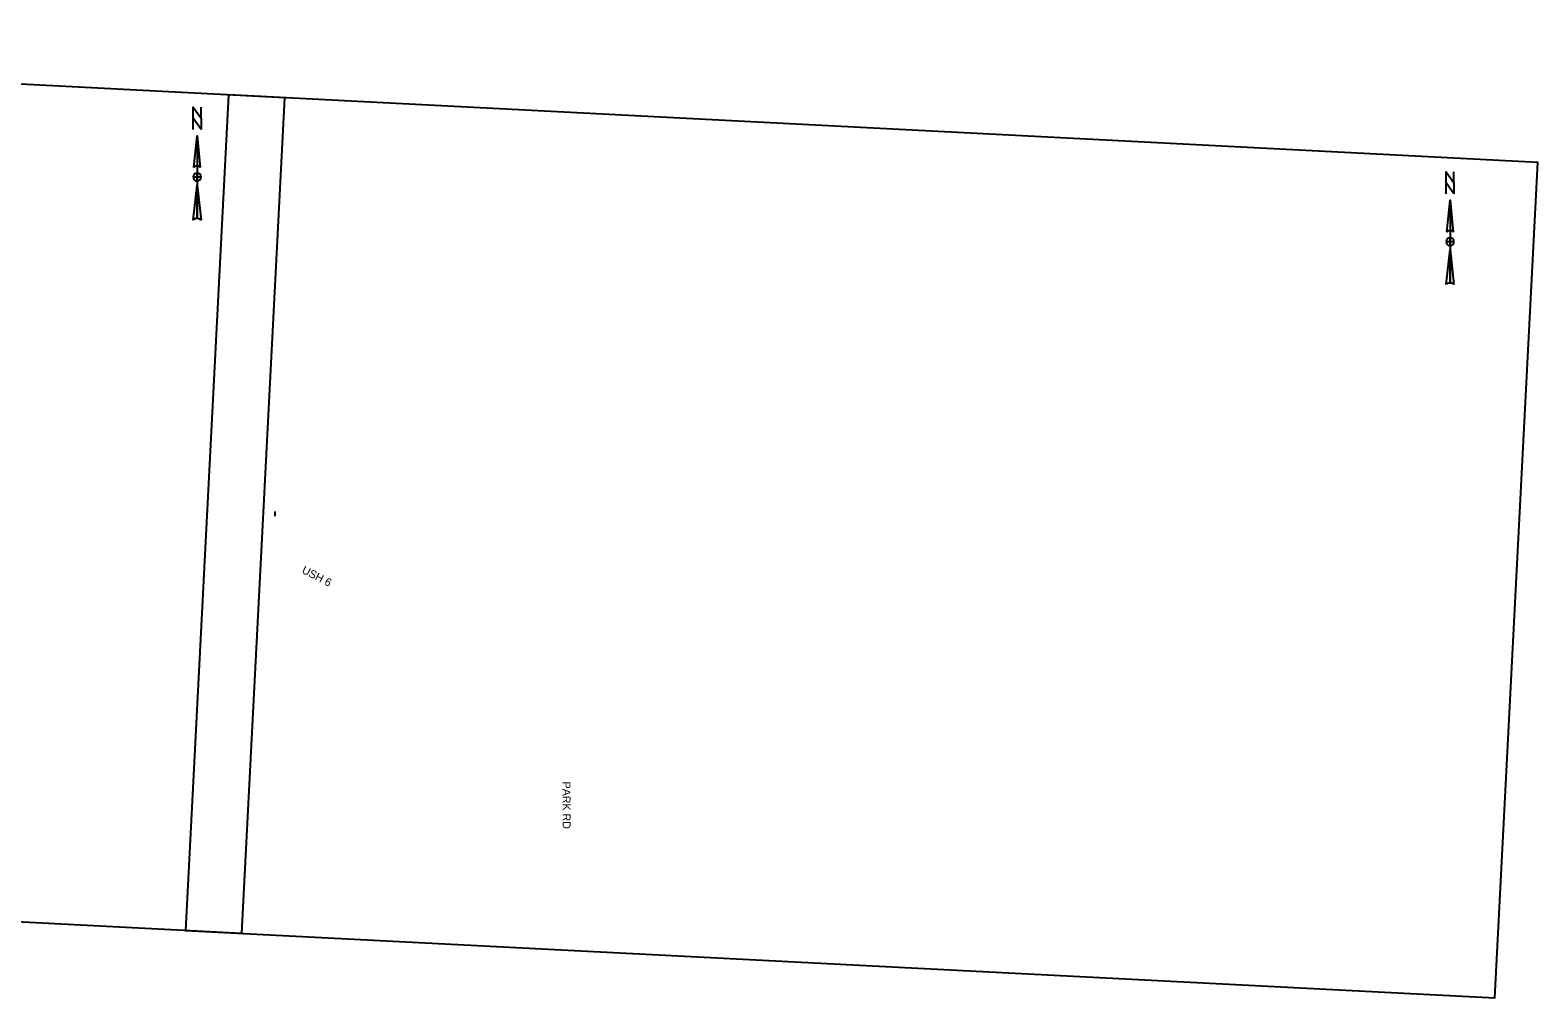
# Model space of a CAD drawing. Extents: x 20499991 to 20505802, y 7953395 to 7954213.
# Drawn here: x 20505081 to 20505802, y 7953395 to 7953857 of the extents above; entities that cross this region are included whole.
import ezdxf

# ---------------------------------------------------------------- set-up
doc = ezdxf.new("R2010")
doc.units = 0
for name, color, linetype in [('brgPreStructureNew', 7, 'Continuous'), ('Drain_Struc_Pr_CB_Std_048in_$Adhoc', 7, 'Continuous'), ('SewerStorm', 7, 'Continuous'), ('SheetText', 7, 'Continuous')]:
    doc.layers.add(name, color=color, linetype=linetype)

msp = doc.modelspace()

# ---------------------------------------------------------------- linework, layer by layer
at = {"layer": 'Drain_Struc_Pr_CB_Std_048in_$Adhoc'}
for points in [[(20504576.26, 7953857.33), (20504555.6, 7953457.86), (20505181.77, 7953425.49), (20505202.42, 7953824.96)], [(20505175.43, 7953826.35), (20505154.83, 7953426.88), (20505781, 7953394.6), (20505801.59, 7953794.07)]]:
    msp.add_lwpolyline(points, close=True, dxfattribs=at)
at = {"layer": 'SewerStorm'}
for p, q in [((20505160.41, 7953806.85), (20505161.93, 7953791.64)), ((20505160.41, 7953806.85), (20505160.41, 7953767.3)), ((20505158.89, 7953791.64), (20505158.89, 7953791.64)), ((20505158.94, 7953791.78), (20505159.23, 7953792.1)), ((20505158.51, 7953766.54), (20505160.41, 7953783.27)), ((20505160.41, 7953785.17), (20505160.41, 7953785.17)), ((20505759.59, 7953775.96), (20505761.11, 7953760.74)), ((20505759.59, 7953775.96), (20505759.59, 7953736.4)), ((20505758.07, 7953760.74), (20505758.07, 7953760.74)), ((20505758.13, 7953760.89), (20505758.41, 7953761.2)), ((20505757.69, 7953735.64), (20505759.59, 7953752.38)), ((20505759.59, 7953754.28), (20505759.59, 7953754.28))]:
    msp.add_line(p, q, dxfattribs=at)
for points in [[(20505162.31, 7953809.89), (20505158.51, 7953815.22), (20505158.51, 7953820.54), (20505162.31, 7953815.22)], [(20505761.49, 7953779), (20505757.69, 7953784.32), (20505757.69, 7953789.65), (20505761.49, 7953784.32)]]:
    msp.add_lwpolyline(points, close=True, dxfattribs=at)
for points in [[(20505158.51, 7953809.89), (20505158.51, 7953820.54), (20505162.31, 7953815.22), (20505162.31, 7953820.54)], [(20505158.89, 7953791.64), (20505160.41, 7953806.85), (20505160.41, 7953792.4)], [(20505160.41, 7953785.17), (20505160.41, 7953787.08), (20505158.51, 7953787.08)], [(20505162.31, 7953787.08), (20505160.41, 7953787.08), (20505160.41, 7953788.98)], [(20505757.69, 7953779), (20505757.69, 7953789.65), (20505761.49, 7953784.32), (20505761.49, 7953789.65)], [(20505160.41, 7953767.3), (20505160.41, 7953783.27), (20505162.31, 7953766.54)], [(20505758.07, 7953760.74), (20505759.59, 7953775.96), (20505759.59, 7953761.5)], [(20505761.49, 7953756.18), (20505759.59, 7953756.18), (20505759.59, 7953758.08)], [(20505759.59, 7953754.28), (20505759.59, 7953756.18), (20505757.69, 7953756.18)], [(20505759.59, 7953736.4), (20505759.59, 7953752.38), (20505761.49, 7953735.64)]]:
    msp.add_lwpolyline(points, dxfattribs=at)
for centre, radius, start, end in [((20505160.41, 7953787.08), 1.9, 90, 180), ((20505160.41, 7953787.08), 1.9, 180, 270), ((20505160.41, 7953790.5), 1.9, 90.02039, 143.12574), ((20505160.41, 7953790.5), 1.9, 36.84806, 90.02184), ((20505160.41, 7953787.08), 1.9, 0, 90), ((20505160.41, 7953787.08), 1.9, 270, 360), ((20505160.41, 7953764.54), 2.76, 89.98939, 133.61895), ((20505160.41, 7953764.54), 2.76, 46.40206, 90.00064), ((20505759.59, 7953756.18), 1.9, 90, 180), ((20505759.59, 7953759.6), 1.9, 90.02039, 143.12574), ((20505759.59, 7953759.6), 1.9, 36.84806, 90.02184), ((20505759.59, 7953756.18), 1.9, 0, 90), ((20505759.59, 7953756.18), 1.9, 180, 270), ((20505759.59, 7953756.18), 1.9, 270, 360), ((20505759.59, 7953733.65), 2.76, 89.98939, 133.61895), ((20505759.59, 7953733.65), 2.76, 46.40206, 90.00064)]:
    msp.add_arc(centre, radius, start, end, dxfattribs=at)
at = {"layer": 'SheetText'}
msp.add_line((20505197.68, 7953624.94), (20505197.8, 7953627.12), dxfattribs=at)

# ---------------------------------------------------------------- texts
at = {"layer": 'brgPreStructureNew'}
for s, rotation, p in [('USH 6', 332.63017, (20505210.15, 7953597.97)), ('PARK RD', 270.24844, (20505335.14, 7953497.99))]:
    msp.add_text(s, height=3.81, rotation=rotation, dxfattribs=at).set_placement(p)

doc.saveas('drawing.dxf')
